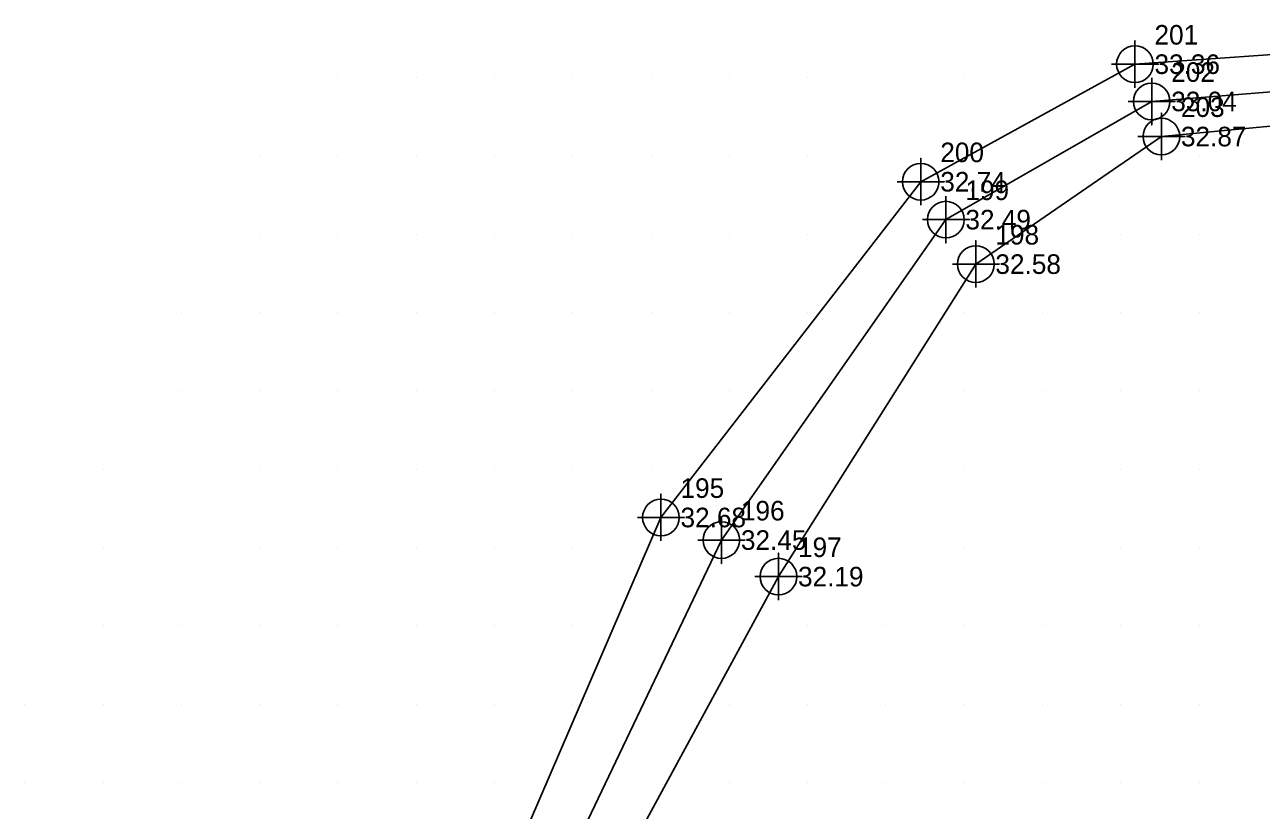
# Model space of a CAD drawing. Extents: x 2204340 to 2204783, y 268170 to 268760.
# Drawn here: x 2204490 to 2204647.9, y 268536.4 to 268636.7 of the extents above; entities that cross this region are included whole.
import ezdxf

# ---------------------------------------------------------------- set-up
doc = ezdxf.new("R2010")
doc.units = 0
for name, color, linetype in [('Exist DTM Crownline', 7, 'Continuous'), ('Exist DTM Crownline Cogo Elevation', 7, 'Continuous'), ('Exist DTM Crownline Cogo Number', 7, 'Continuous'), ('Exist DTM Crownline Cogo Point CELL', 7, 'Continuous'), ('Exist DTM QL2 LIDAR Elevation Point', 7, 'Continuous'), ('Exist Roads Soil', 7, 'Continuous'), ('Exist Roads Soil Cogo Elevation', 7, 'Continuous'), ('Exist Roads Soil Cogo Number', 7, 'Continuous'), ('Exist Roads Soil Cogo Point CELL', 7, 'Continuous')]:
    doc.layers.add(name, color=color, linetype=linetype)

msp = doc.modelspace()

# ---------------------------------------------------------------- linework, layer by layer
at = {"layer": 'Exist DTM Crownline'}
msp.add_lwpolyline([(2204544.57, 268496.57), (2204544.8, 268497.2), (2204557.39, 268525.73), (2204578.98, 268570.95), (2204607.65, 268611.86), (2204633.94, 268626.95), (2204664.49, 268629.4), (2204716.63, 268622.98), (2204771.01, 268618.5)], dxfattribs=at)
at = {"layer": 'Exist DTM Crownline Cogo Point CELL'}
for points in [[(2204633.94, 268629.95), (2204633.94, 268623.95), (2204633.94, 268626.95), (2204636.94, 268626.95), (2204630.94, 268626.95)], [(2204607.65, 268614.86), (2204607.65, 268608.86), (2204607.65, 268611.86), (2204610.65, 268611.86), (2204604.65, 268611.86)], [(2204578.98, 268573.95), (2204578.98, 268567.95), (2204578.98, 268570.95), (2204581.98, 268570.95), (2204575.98, 268570.95)]]:
    msp.add_lwpolyline(points, dxfattribs=at)
for centre in [(2204633.94, 268626.95), (2204607.65, 268611.86), (2204578.98, 268570.95)]:
    msp.add_circle(centre, 2.34, dxfattribs=at)
at = {"layer": 'Exist DTM QL2 LIDAR Elevation Point'}
for p, q in [((2204530, 268630), (2204530, 268630)), ((2204540, 268630), (2204540, 268630)), ((2204550, 268630), (2204550, 268630)), ((2204560, 268630), (2204560, 268630)), ((2204570, 268630), (2204570, 268630)), ((2204580, 268630), (2204580, 268630)), ((2204590, 268630), (2204590, 268630)), ((2204600, 268630), (2204600, 268630)), ((2204610, 268630), (2204610, 268630)), ((2204620, 268630), (2204620, 268630)), ((2204520, 268620), (2204520, 268620)), ((2204530, 268620), (2204530, 268620)), ((2204540, 268620), (2204540, 268620)), ((2204550, 268620), (2204550, 268620)), ((2204560, 268620), (2204560, 268620)), ((2204570, 268620), (2204570, 268620)), ((2204580, 268620), (2204580, 268620)), ((2204590, 268620), (2204590, 268620)), ((2204600, 268620), (2204600, 268620)), ((2204640, 268620), (2204640, 268620)), ((2204520, 268610), (2204520, 268610)), ((2204530, 268610), (2204530, 268610)), ((2204540, 268610), (2204540, 268610)), ((2204550, 268610), (2204550, 268610)), ((2204560, 268610), (2204560, 268610)), ((2204570, 268610), (2204570, 268610)), ((2204580, 268610), (2204580, 268610)), ((2204590, 268610), (2204590, 268610)), ((2204620, 268610), (2204620, 268610)), ((2204630, 268610), (2204630, 268610)), ((2204640, 268610), (2204640, 268610)), ((2204510, 268600), (2204510, 268600)), ((2204520, 268600), (2204520, 268600)), ((2204530, 268600), (2204530, 268600)), ((2204540, 268600), (2204540, 268600)), ((2204550, 268600), (2204550, 268600)), ((2204560, 268600), (2204560, 268600)), ((2204570, 268600), (2204570, 268600)), ((2204580, 268600), (2204580, 268600)), ((2204590, 268600), (2204590, 268600)), ((2204610, 268600), (2204610, 268600)), ((2204620, 268600), (2204620, 268600)), ((2204630, 268600), (2204630, 268600)), ((2204640, 268600), (2204640, 268600)), ((2204510, 268590), (2204510, 268590)), ((2204520, 268590), (2204520, 268590)), ((2204530, 268590), (2204530, 268590)), ((2204540, 268590), (2204540, 268590)), ((2204550, 268590), (2204550, 268590)), ((2204560, 268590), (2204560, 268590)), ((2204570, 268590), (2204570, 268590)), ((2204580, 268590), (2204580, 268590)), ((2204610, 268590), (2204610, 268590)), ((2204620, 268590), (2204620, 268590)), ((2204630, 268590), (2204630, 268590)), ((2204640, 268590), (2204640, 268590)), ((2204500, 268580), (2204500, 268580)), ((2204510, 268580), (2204510, 268580)), ((2204520, 268580), (2204520, 268580)), ((2204530, 268580), (2204530, 268580)), ((2204540, 268580), (2204540, 268580)), ((2204550, 268580), (2204550, 268580)), ((2204560, 268580), (2204560, 268580)), ((2204570, 268580), (2204570, 268580)), ((2204600, 268580), (2204600, 268580)), ((2204610, 268580), (2204610, 268580)), ((2204620, 268580), (2204620, 268580)), ((2204630, 268580), (2204630, 268580)), ((2204640, 268580), (2204640, 268580)), ((2204500, 268570), (2204500, 268570)), ((2204510, 268570), (2204510, 268570)), ((2204520, 268570), (2204520, 268570)), ((2204530, 268570), (2204530, 268570)), ((2204540, 268570), (2204540, 268570)), ((2204550, 268570), (2204550, 268570)), ((2204560, 268570), (2204560, 268570)), ((2204590, 268570), (2204590, 268570)), ((2204600, 268570), (2204600, 268570)), ((2204610, 268570), (2204610, 268570)), ((2204620, 268570), (2204620, 268570)), ((2204630, 268570), (2204630, 268570)), ((2204640, 268570), (2204640, 268570)), ((2204500, 268560), (2204500, 268560)), ((2204510, 268560), (2204510, 268560)), ((2204520, 268560), (2204520, 268560)), ((2204530, 268560), (2204530, 268560)), ((2204540, 268560), (2204540, 268560)), ((2204550, 268560), (2204550, 268560)), ((2204560, 268560), (2204560, 268560)), ((2204590, 268560), (2204590, 268560)), ((2204600, 268560), (2204600, 268560)), ((2204610, 268560), (2204610, 268560)), ((2204620, 268560), (2204620, 268560)), ((2204630, 268560), (2204630, 268560)), ((2204640, 268560), (2204640, 268560)), ((2204490, 268550), (2204490, 268550)), ((2204500, 268550), (2204500, 268550)), ((2204510, 268550), (2204510, 268550)), ((2204520, 268550), (2204520, 268550)), ((2204530, 268550), (2204530, 268550)), ((2204540, 268550), (2204540, 268550)), ((2204550, 268550), (2204550, 268550)), ((2204560, 268550), (2204560, 268550)), ((2204580, 268550), (2204580, 268550)), ((2204590, 268550), (2204590, 268550)), ((2204600, 268550), (2204600, 268550)), ((2204610, 268550), (2204610, 268550)), ((2204620, 268550), (2204620, 268550)), ((2204630, 268550), (2204630, 268550)), ((2204640, 268550), (2204640, 268550)), ((2204490, 268540), (2204490, 268540)), ((2204500, 268540), (2204500, 268540)), ((2204510, 268540), (2204510, 268540)), ((2204520, 268540), (2204520, 268540)), ((2204530, 268540), (2204530, 268540)), ((2204540, 268540), (2204540, 268540)), ((2204550, 268540), (2204550, 268540)), ((2204580, 268540), (2204580, 268540)), ((2204590, 268540), (2204590, 268540)), ((2204600, 268540), (2204600, 268540)), ((2204610, 268540), (2204610, 268540)), ((2204620, 268540), (2204620, 268540)), ((2204630, 268540), (2204630, 268540)), ((2204640, 268540), (2204640, 268540))]:
    msp.add_line(p, q, dxfattribs=at)
at = {"layer": 'Exist Roads Soil'}
for points in [[(2204539.85, 268499.13), (2204551.95, 268529.07), (2204571.26, 268573.83), (2204604.44, 268616.7), (2204631.8, 268631.71), (2204665.76, 268634.11), (2204716.61, 268627.31), (2204772.22, 268623.54)], [(2204549.08, 268494.18), (2204563.25, 268523.88), (2204586.27, 268566.28), (2204611.48, 268606.18), (2204635.18, 268622.47), (2204662.53, 268625.07), (2204716.08, 268618.66), (2204769.53, 268613.44)]]:
    msp.add_lwpolyline(points, dxfattribs=at)
at = {"layer": 'Exist Roads Soil Cogo Point CELL'}
for points in [[(2204631.8, 268628.71), (2204631.8, 268634.71), (2204631.8, 268631.71), (2204634.8, 268631.71), (2204628.8, 268631.71)], [(2204635.18, 268619.47), (2204635.18, 268625.47), (2204635.18, 268622.47), (2204638.18, 268622.47), (2204632.18, 268622.47)], [(2204604.44, 268613.7), (2204604.44, 268619.7), (2204604.44, 268616.7), (2204607.44, 268616.7), (2204601.44, 268616.7)], [(2204611.48, 268603.18), (2204611.48, 268609.18), (2204611.48, 268606.18), (2204614.48, 268606.18), (2204608.48, 268606.18)], [(2204571.26, 268570.83), (2204571.26, 268576.83), (2204571.26, 268573.83), (2204574.26, 268573.83), (2204568.26, 268573.83)], [(2204586.27, 268563.28), (2204586.27, 268569.28), (2204586.27, 268566.28), (2204589.27, 268566.28), (2204583.27, 268566.28)]]:
    msp.add_lwpolyline(points, dxfattribs=at)
for centre in [(2204631.8, 268631.71), (2204635.18, 268622.47), (2204604.44, 268616.7), (2204611.48, 268606.18), (2204571.26, 268573.83), (2204586.27, 268566.28)]:
    msp.add_circle(centre, 2.34, dxfattribs=at)

# ---------------------------------------------------------------- texts
at = {"layer": 'Exist DTM Crownline Cogo Elevation'}
for s, p in [('33.04', (2204636.44, 268625.7)), ('32.49', (2204610.15, 268610.61)), ('32.45', (2204581.48, 268569.7))]:
    msp.add_text(s, height=2.5, dxfattribs=at).set_placement(p)
at = {"layer": 'Exist DTM Crownline Cogo Number'}
for s, p in [('202', (2204636.44, 268629.45)), ('199', (2204610.15, 268614.36)), ('196', (2204581.48, 268573.45))]:
    msp.add_text(s, height=2.5, dxfattribs=at).set_placement(p)
at = {"layer": 'Exist Roads Soil Cogo Elevation'}
for s, p in [('33.36', (2204634.3, 268630.46)), ('32.87', (2204637.68, 268621.22)), ('32.74', (2204606.94, 268615.45)), ('32.58', (2204613.98, 268604.93)), ('32.68', (2204573.76, 268572.58)), ('32.19', (2204588.77, 268565.03))]:
    msp.add_text(s, height=2.5, dxfattribs=at).set_placement(p)
at = {"layer": 'Exist Roads Soil Cogo Number'}
for s, p in [('201', (2204634.3, 268634.21)), ('203', (2204637.68, 268624.97)), ('200', (2204606.94, 268619.2)), ('198', (2204613.98, 268608.68)), ('195', (2204573.76, 268576.33)), ('197', (2204588.77, 268568.78))]:
    msp.add_text(s, height=2.5, dxfattribs=at).set_placement(p)

doc.saveas('drawing.dxf')
